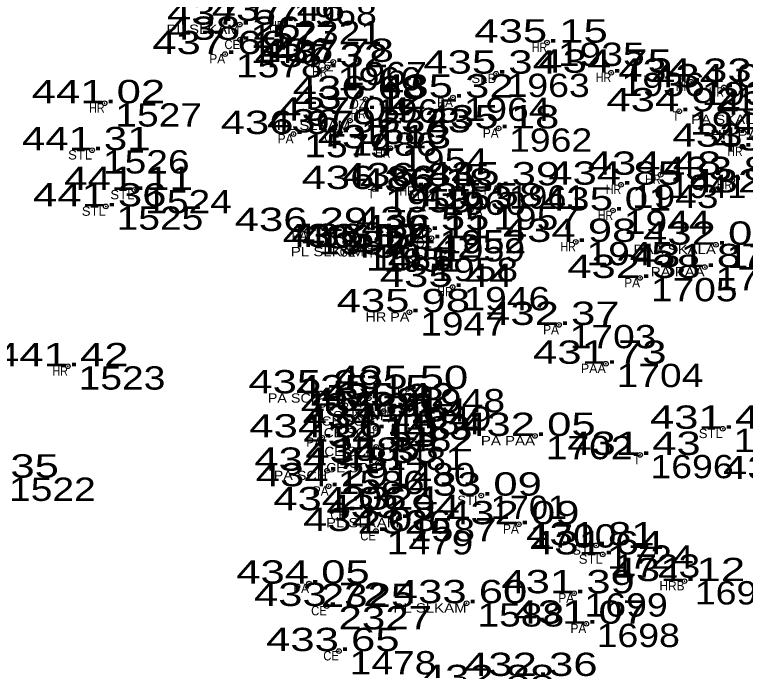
# Model space of a CAD drawing. Extents: x -639390 to -639074, y -1138747 to -1138358.
# Drawn here: x -639287.05 to -639263.54, y -1138562.27 to -1138541.18 of the extents above; entities that cross this region are included whole.
import ezdxf
from ezdxf.enums import TextEntityAlignment as Align

# ---------------------------------------------------------------- set-up
doc = ezdxf.new("R2010")
doc.units = 0
doc.header["$LTSCALE"] = 0.3
doc.header["$PDMODE"] = 32
doc.header["$PDSIZE"] = 0.15
for name, color, linetype in [('11', 7, 'Continuous'), ('12', 7, 'Continuous'), ('13', 7, 'Continuous'), ('57', 7, 'Continuous')]:
    doc.layers.add(name, color=color, linetype=linetype)

msp = doc.modelspace()

# ---------------------------------------------------------------- linework, layer by layer
at = {"layer": '11'}
for p in [(-639278.37, -1138541.38), (-639279.81, -1138541.5), (-639279.8, -1138541.99), (-639269.92, -1138542.08), (-639280.28, -1138542.45), (-639276.99, -1138542.87), (-639276.8, -1138542.7), (-639271.56, -1138543.08), (-639267.86, -1138543.05), (-639265.29, -1138543.34), (-639264.23, -1138543.52), (-639284.16, -1138544.03), (-639275.76, -1138543.9), (-639272.95, -1138543.85), (-639275.75, -1138544.22), (-639265.67, -1138544.29), (-639276.26, -1138544.59), (-639276.59, -1138544.97), (-639271.48, -1138544.84), (-639278.08, -1138545.02), (-639263.63, -1138545.43), (-639284.56, -1138545.54), (-639274.96, -1138545.48), (-639266.27, -1138546.33), (-639263.97, -1138546.5), (-639283.2, -1138546.82), (-639275.48, -1138546.79), (-639274.18, -1138546.7), (-639271.45, -1138546.67), (-639267.54, -1138546.65), (-639273.6, -1138546.87), (-639284.12, -1138547.35), (-639272, -1138547.35), (-639267.8, -1138547.48), (-639277.63, -1138548.14), (-639273.73, -1138548.11), (-639273.64, -1138548.37), (-639269, -1138548.49), (-639276.09, -1138548.66), (-639275.81, -1138548.65), (-639275.48, -1138548.7), (-639264.49, -1138548.58), (-639273.99, -1138549), (-639264.85, -1138549.3), (-639266.93, -1138549.65), (-639272.96, -1138549.94), (-639274.35, -1138550.75), (-639269.54, -1138551.16), (-639285.34, -1138552.49), (-639268.03, -1138552.41), (-639277.19, -1138553.36), (-639274.41, -1138553.22), (-639275.66, -1138553.52), (-639274.84, -1138553.78), (-639275.51, -1138554.1), (-639275.18, -1138553.93), (-639275.44, -1138554.48), (-639264.27, -1138554.5), (-639277.16, -1138554.78), (-639270.31, -1138554.73), (-639275.42, -1138555.08), (-639266.93, -1138555.34), (-639275.36, -1138555.6), (-639277, -1138555.85), (-639276.95, -1138556.35), (-639272.04, -1138556.65), (-639276.39, -1138557.12), (-639274.68, -1138557.37), (-639270.83, -1138557.57), (-639275.43, -1138557.79), (-639268.34, -1138558.25), (-639268.13, -1138558.54), (-639277.58, -1138559.48), (-639265.5, -1138559.4), (-639269.05, -1138559.79), (-639277.01, -1138560.2), (-639272.51, -1138560.11), (-639268.66, -1138560.77), (-639276.62, -1138561.65)]:
    msp.add_point(p, dxfattribs=at)

# ---------------------------------------------------------------- texts
at = {"layer": '12'}
for s, width, p in [('437.46 ', 1.4, (-639278.369, -1138541.38)), ('437.67 ', 1.4, (-639279.81, -1138541.5)), ('438.26 ', 1.4, (-639279.799, -1138541.99)), ('435.15 ', 1.4, (-639269.92, -1138542.08)), ('437.69 ', 1.4, (-639280.28, -1138542.45)), ('436.78 ', 1.4, (-639276.8, -1138542.7)), ('437.32 ', 1.4, (-639276.99, -1138542.87)), ('435.34 ', 1.4, (-639271.56, -1138543.08)), ('434.75 ', 1.4, (-639267.86, -1138543.05)), ('434.33 ', 1.4, (-639265.29, -1138543.34)), ('434.08 ', 1.4, (-639264.23, -1138543.52)), ('436.68 ', 1.4, (-639275.76, -1138543.9)), ('435.32 ', 1.4, (-639272.95, -1138543.85)), ('441.02 ', 1.4, (-639284.16, -1138544.03)), ('437.12 ', 1.4, (-639275.75, -1138544.22)), ('434.92 ', 1.4, (-639265.67, -1138544.29)), ('431.69 ', 1.4, (-639262.13, -1138544.4)), ('437.04 ', 1.4, (-639276.26, -1138544.59)), ('435.18 ', 1.4, (-639271.48, -1138544.84)), ('436.97 ', 1.4, (-639278.08, -1138545.02)), ('436.96 ', 1.4, (-639276.589, -1138544.97)), ('433.91 ', 1.35, (-639263.629, -1138545.43)), ('441.31 ', 1.35, (-639284.559, -1138545.54)), ('437.13 ', 1.4, (-639274.96, -1138545.48)), ('431.92 ', 1.4, (-639262.22, -1138545.55)), ('434.48 ', 1.4, (-639266.27, -1138546.33)), ('433.81 ', 1.35, (-639263.969, -1138546.5)), ('441.11 ', 1.35, (-639283.199, -1138546.82)), ('436.86 ', 1.4, (-639275.479, -1138546.79)), ('436.84 ', 1.4, (-639274.18, -1138546.7)), ('435.39 ', 1.4, (-639271.45, -1138546.67)), ('434.85 ', 1.4, (-639267.54, -1138546.65)), ('436.18 ', 1.4, (-639273.6, -1138546.87)), ('432.12 ', 1.4, (-639263, -1138546.9)), ('441.36 ', 1.4, (-639284.119, -1138547.35)), ('435.58 ', 1.4, (-639272, -1138547.35)), ('435.01 ', 1.35, (-639267.799, -1138547.48)), ('436.29 ', 1.4, (-639277.63, -1138548.14)), ('436.55 ', 1.4, (-639273.73, -1138548.11)), ('436.11 ', 1.35, (-639273.639, -1138548.37)), ('434.98 ', 1.4, (-639269, -1138548.49)), ('436.19 ', 1.4, (-639276.09, -1138548.66)), ('436.17 ', 1.4, (-639275.81, -1138548.65)), ('436.54 ', 1.4, (-639275.48, -1138548.7)), ('432.06 ', 1.4, (-639264.489, -1138548.58)), ('436.42 ', 1.4, (-639273.99, -1138549)), ('431.87 ', 1.4, (-639264.85, -1138549.3)), ('432.38 ', 1.4, (-639266.93, -1138549.65)), ('435.44 ', 1.4, (-639272.96, -1138549.94)), ('435.98 ', 1.4, (-639274.35, -1138550.75)), ('432.37 ', 1.4, (-639269.54, -1138551.16)), ('441.42 ', 1.4, (-639285.34, -1138552.49)), ('431.73 ', 1.4, (-639268.03, -1138552.41)), ('435.29 ', 1.4, (-639277.19, -1138553.36)), ('435.50 ', 1.4, (-639274.41, -1138553.22)), ('435.15 ', 1.4, (-639275.66, -1138553.52)), ('435.42 ', 1.4, (-639274.84, -1138553.78)), ('434.96 ', 1.4, (-639275.509, -1138554.1)), ('434.98 ', 1.4, (-639275.18, -1138553.93)), ('434.74 ', 1.4, (-639275.44, -1138554.48)), ('431.42 ', 1.4, (-639264.27, -1138554.5)), ('434.86 ', 1.4, (-639277.159, -1138554.78)), ('432.05 ', 1.4, (-639270.31, -1138554.73)), ('434.53 ', 1.4, (-639275.42, -1138555.08)), ('431.43 ', 1.4, (-639266.93, -1138555.34)), ('434.35 ', 1.4, (-639275.36, -1138555.6)), ('434.43 ', 1.4, (-639277, -1138555.85)), ('441.35 ', 1.4, (-639287.58, -1138556.07)), ('430.87 ', 1.4, (-639261.92, -1138556.12)), ('434.29 ', 1.4, (-639276.95, -1138556.35)), ('433.09 ', 1.4, (-639272.04, -1138556.65)), ('434.06 ', 1.4, (-639276.389, -1138557.12)), ('433.94 ', 1.4, (-639274.68, -1138557.37)), ('432.09 ', 1.4, (-639270.83, -1138557.57)), ('434.03 ', 1.4, (-639275.43, -1138557.79)), ('431.81 ', 1.35, (-639268.339, -1138558.25)), ('431.64 ', 1.4, (-639268.13, -1138558.54)), ('434.05 ', 1.4, (-639277.58, -1138559.48)), ('431.12 ', 1.4, (-639265.5, -1138559.4)), ('431.39 ', 1.4, (-639269.05, -1138559.79)), ('433.72 ', 1.4, (-639277.01, -1138560.2)), ('433.60 ', 1.4, (-639272.51, -1138560.11)), ('431.07 ', 1.4, (-639268.66, -1138560.77)), ('433.65 ', 1.4, (-639276.62, -1138561.65)), ('432.36 ', 1.4, (-639270.249, -1138562.45)), ('432.88 ', 1.4, (-639271.64, -1138562.84))]:
    msp.add_text(s, height=0.75, dxfattribs=dict(at, width=width)).set_placement(p, align=Align.CENTER)
at = {"layer": '13'}
for s, width, p in [(' 1968', 1.2, (-639278.41, -1138541.53)), (' 2321', 1.25, (-639278.37, -1138542.13)), (' 1577', 1.25, (-639279.81, -1138542.25)), (' 1487', 1.25, (-639279.8, -1138542.74)), (' 1935', 1.25, (-639269.92, -1138542.83)), (' 1578', 1.25, (-639280.28, -1138543.2)), (' 1967', 1.2, (-639276.8, -1138543.45)), (' 1966', 1.2, (-639276.99, -1138543.62)), (' 1963', 1.2, (-639271.56, -1138543.83)), (' 1936', 1.2, (-639267.86, -1138543.8)), (' 1937', 1.25, (-639265.29, -1138544.09)), (' 1938', 1.25, (-639264.23, -1138544.27)), (' 1965', 1.2, (-639275.76, -1138544.65)), (' 1964', 1.25, (-639272.95, -1138544.6)), (' 1527', 1.25, (-639284.16, -1138544.78)), (' 2323', 1.35, (-639275.75, -1138544.97)), (' 1942', 1.25, (-639265.67, -1138545.04)), (' 1580', 1.25, (-639276.26, -1138545.34)), (' 1962', 1.2, (-639271.48, -1138545.59)), (' 1579', 1.25, (-639278.08, -1138545.77)), (' 1486', 1.25, (-639276.59, -1138545.72)), (' 1526', 1.25, (-639284.56, -1138546.29)), (' 1954', 1.25, (-639274.96, -1138546.23)), (' 1941', 1.1, (-639266.27, -1138547.08)), (' 1955', 1.25, (-639275.48, -1138547.54)), (' 1953', 1.25, (-639274.18, -1138547.45)), (' 1961', 1.1, (-639271.45, -1138547.42)), (' 1943', 1.25, (-639267.54, -1138547.4)), (' 1524', 1.25, (-639283.2, -1138547.57)), (' 1960', 1.2, (-639273.6, -1138547.62)), (' 1525', 1.25, (-639284.12, -1138548.1)), (' 1957', 1.25, (-639272, -1138548.1)), (' 1944', 1.25, (-639267.8, -1138548.23)), (' 1582', 1.25, (-639277.63, -1138548.89)), (' 1952', 1.25, (-639273.73, -1138548.86)), (' 1959', 1.2, (-639273.64, -1138549.12)), (' 1485', 1.25, (-639276.09, -1138549.41)), (' 1581', 1.1, (-639275.81, -1138549.4)), (' 1945', 1.25, (-639269, -1138549.24)), (' 1707', 1.25, (-639264.49, -1138549.33)), (' 1951', 1.1, (-639275.48, -1138549.45)), (' 1958', 1.25, (-639273.99, -1138549.75)), (' 1706', 1.25, (-639264.85, -1138550.05)), (' 1705', 1.25, (-639266.93, -1138550.4)), (' 1946', 1.25, (-639272.96, -1138550.69)), (' 1947', 1.25, (-639274.35, -1138551.5)), (' 1703', 1.25, (-639269.54, -1138551.91)), (' 1704', 1.25, (-639268.03, -1138553.16)), (' 1523', 1.25, (-639285.34, -1138553.24)), (' 1583', 1.25, (-639277.19, -1138554.11)), (' 1948', 1.25, (-639274.41, -1138553.97)), (' 1484', 1.25, (-639275.66, -1138554.27)), (' 1949', 1.25, (-639274.84, -1138554.53)), (' 1584', 1.25, (-639275.18, -1138554.68)), (' 1483', 1.25, (-639275.51, -1138554.85)), (' 1482', 1.25, (-639275.44, -1138555.23)), (' 1722', 1.25, (-639264.27, -1138555.25)), (' 1585', 1.25, (-639277.16, -1138555.53)), (' 1702', 1.25, (-639270.31, -1138555.48)), (' 1481', 1.15, (-639275.42, -1138555.83)), (' 1696', 1.2, (-639266.93, -1138556.09)), (' 1480', 1.25, (-639275.36, -1138556.35)), (' 1586', 1.25, (-639277, -1138556.6)), (' 1522', 1.25, (-639287.58, -1138556.82)), (' 2324', 1.4, (-639276.95, -1138557.1)), (' 1701', 1.1, (-639272.04, -1138557.4)), (' 2326', 1.35, (-639276.39, -1138557.87)), (' 1587', 1.25, (-639274.68, -1138558.12)), (' 1700', 1.25, (-639270.83, -1138558.32)), (' 1479', 1.25, (-639275.43, -1138558.54)), (' 1724', 1.25, (-639268.34, -1138559)), (' 1723', 1.25, (-639268.13, -1138559.29)), (' 2325', 1.35, (-639277.58, -1138560.23)), (' 1695', 1.2, (-639265.5, -1138560.15)), (' 1699', 1.2, (-639269.05, -1138560.54)), (' 2327', 1.35, (-639277.01, -1138560.95)), (' 1588', 1.25, (-639272.51, -1138560.86)), (' 1698', 1.2, (-639268.66, -1138561.52)), (' 1478', 1.25, (-639276.62, -1138562.4))]:
    msp.add_text(s, height=0.75, dxfattribs=dict(at, width=width)).set_placement(p)
at = {"layer": '57'}
for s, width, p in [('HR', 0.85, (-639278.369, -1138541.68)), ('PL SLKAM', 1.2, (-639279.81, -1138541.8)), ('CE', 0.9, (-639279.8, -1138542.29)), ('HR', 0.85, (-639269.919, -1138542.38)), ('PA', 0.95, (-639280.28, -1138542.75)), ('OZ', 0.9, (-639276.799, -1138543)), ('HR', 0.85, (-639276.989, -1138543.17)), ('SLB', 1.05, (-639271.559, -1138543.38)), ('HR', 0.85, (-639267.859, -1138543.35)), ('HR', 0.85, (-639265.289, -1138543.64)), ('HR', 0.85, (-639264.229, -1138543.82)), ('OZ', 0.9, (-639275.759, -1138544.2)), ('PA', 0.95, (-639272.95, -1138544.15)), ('HR', 0.85, (-639284.159, -1138544.33)), ('HR', 0.85, (-639275.749, -1138544.52)), ('T', 0.85, (-639265.67, -1138544.59)), ('PA SKALA HR', 1.2, (-639262.129, -1138544.7)), ('PL SLKAM', 1.2, (-639276.26, -1138544.89)), ('PA', 0.95, (-639271.48, -1138545.14)), ('HR PAA PA SKALA', 1.25, (-639260.23, -1138545.19)), ('PA', 0.95, (-639278.08, -1138545.32)), ('CE', 0.9, (-639276.59, -1138545.27)), ('STL', 1.05, (-639284.559, -1138545.84)), ('HR', 0.85, (-639274.959, -1138545.78)), ('HR', 0.85, (-639263.629, -1138545.73)), ('HR', 0.85, (-639266.269, -1138546.63)), ('HR', 0.85, (-639263.969, -1138546.8)), ('T', 0.85, (-639275.48, -1138547.09)), ('HR', 0.85, (-639274.179, -1138547)), ('PA', 0.95, (-639271.45, -1138546.97)), ('HR', 0.85, (-639267.539, -1138546.95)), ('STL', 1.05, (-639283.199, -1138547.12)), ('OZ', 0.9, (-639273.599, -1138547.17)), ('STL', 1.05, (-639284.119, -1138547.65)), ('PA', 0.95, (-639272, -1138547.65)), ('HR', 0.85, (-639267.799, -1138547.78)), ('PA', 0.95, (-639277.63, -1138548.44)), ('HR', 0.85, (-639273.729, -1138548.41)), ('OZ', 0.9, (-639273.639, -1138548.67)), ('PL SLKAM', 1.2, (-639275.81, -1138548.95)), ('CE', 0.9, (-639276.09, -1138548.96)), ('HR', 0.85, (-639268.999, -1138548.79)), ('PAA SKALA', 1.2, (-639264.49, -1138548.88)), ('T', 0.85, (-639275.48, -1138549)), ('OZ', 0.9, (-639273.989, -1138549.3)), ('PA PAA', 1.2, (-639264.85, -1138549.6)), ('PA', 0.95, (-639266.93, -1138549.95)), ('HR', 0.85, (-639272.959, -1138550.24)), ('HR PA', 1.15, (-639274.35, -1138551.05)), ('PA', 0.95, (-639269.54, -1138551.46)), ('HR', 0.85, (-639285.339, -1138552.79)), ('PA SCH', 1.15, (-639277.189, -1138553.66)), ('HR', 0.85, (-639274.409, -1138553.52)), ('CE SCH', 1.1, (-639275.659, -1138553.82)), ('HR', 0.85, (-639274.839, -1138554.08)), ('PL SLKAM', 1.2, (-639275.18, -1138554.23)), ('CE SCH', 1.1, (-639275.509, -1138554.4)), ('CE SCH', 1.1, (-639275.439, -1138554.78)), ('STL', 1.05, (-639264.269, -1138554.8)), ('PA', 0.95, (-639277.16, -1138555.08)), ('PA PAA', 1.2, (-639270.31, -1138555.03)), ('CE SCH', 1.1, (-639275.419, -1138555.38)), ('T', 0.85, (-639266.93, -1138555.64)), ('CE SCH', 1.1, (-639275.359, -1138555.9)), ('PA SCH', 1.15, (-639276.999, -1138556.15)), ('PA', 0.95, (-639276.95, -1138556.65)), ('STL', 1.05, (-639272.039, -1138556.95)), ('CE', 0.9, (-639276.39, -1138557.42)), ('PL SLKAM', 1.2, (-639274.68, -1138557.67)), ('PA', 0.95, (-639270.83, -1138557.87)), ('CE', 0.9, (-639275.43, -1138558.09)), ('STL', 1.05, (-639268.339, -1138558.55)), ('STL', 1.05, (-639268.129, -1138558.84)), ('PA', 0.95, (-639277.58, -1138559.78)), ('HRB', 0.95, (-639265.499, -1138559.7)), ('PA', 0.95, (-639269.05, -1138560.09)), ('CE', 0.9, (-639277.01, -1138560.5)), ('PL SLKAM', 1.2, (-639272.51, -1138560.41)), ('PA', 0.95, (-639268.66, -1138561.07)), ('CE', 0.9, (-639276.62, -1138561.95))]:
    msp.add_text(s, height=0.3, dxfattribs=dict(at, width=width)).set_placement(p, align=Align.RIGHT)
msp.add_text('PAA', height=0.3, dxfattribs=at).set_placement((-639268.03, -1138552.71), align=Align.RIGHT)

doc.saveas('drawing.dxf')
